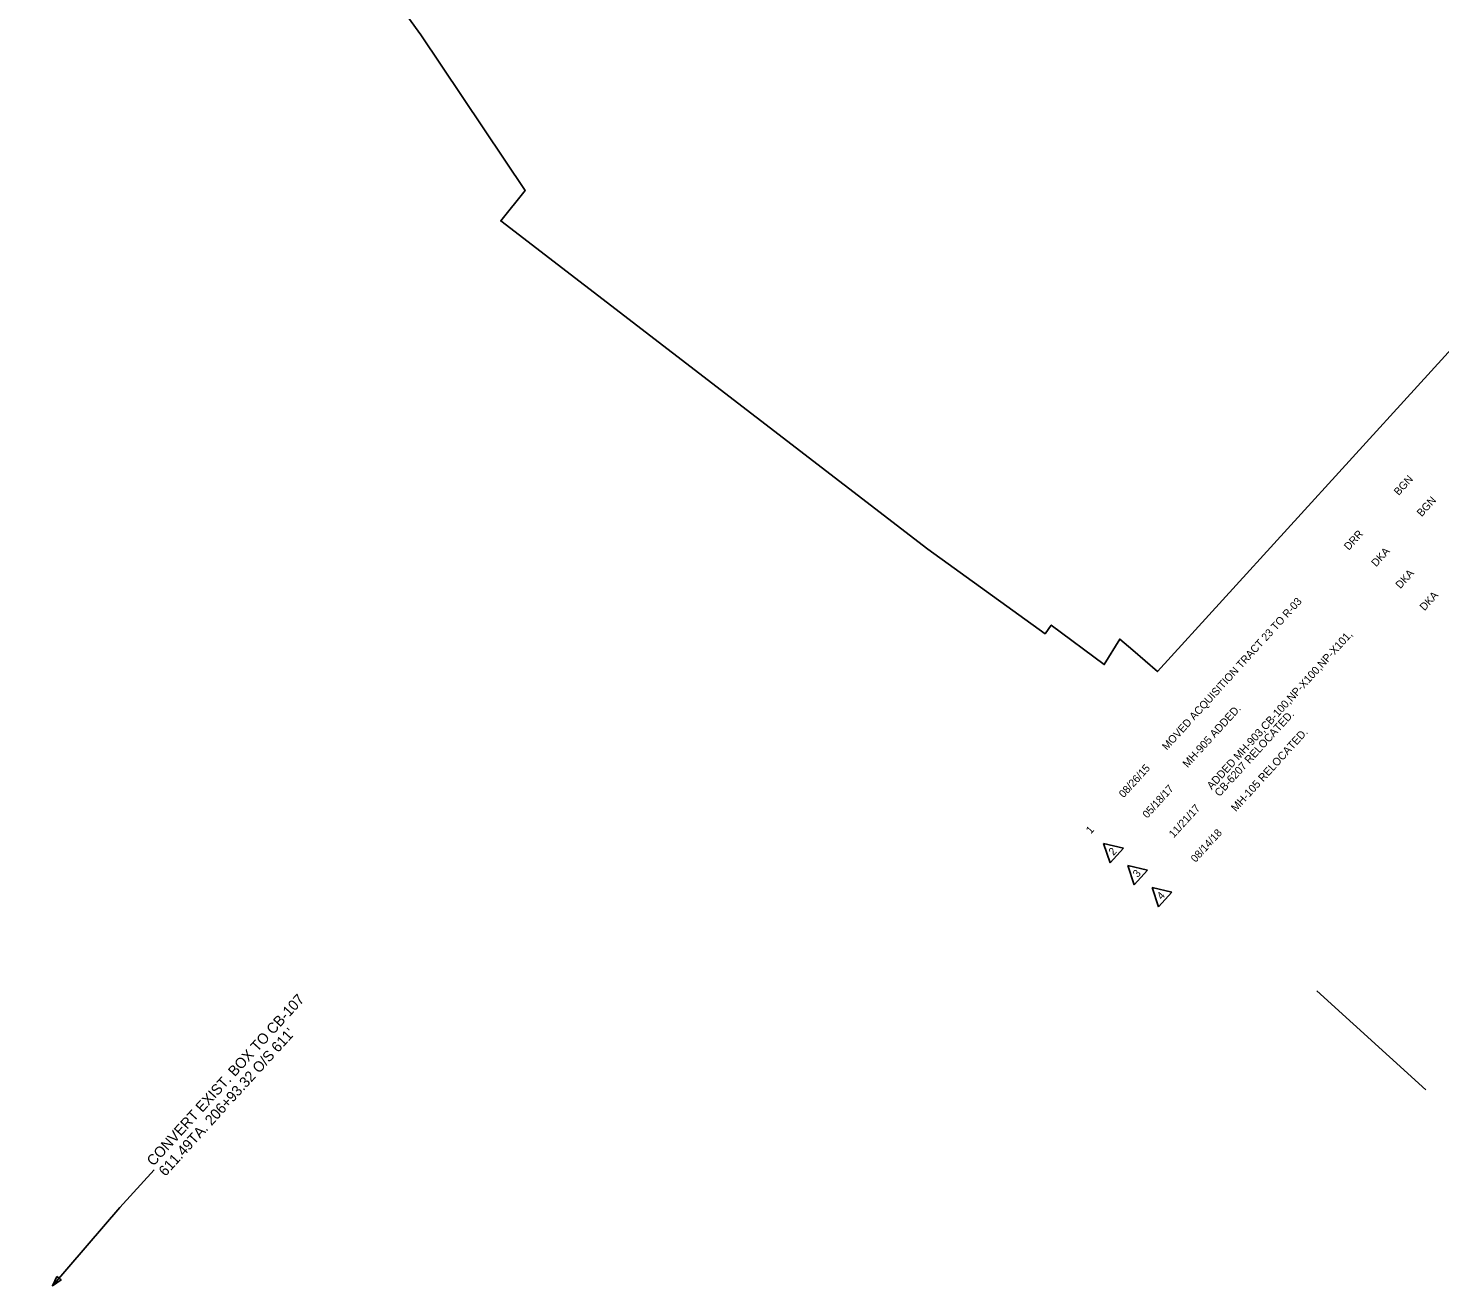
# Model space of a CAD drawing. Extents: x 1608866 to 1610566, y 1091738 to 1093850.
# Drawn here: x 1608866 to 1609672, y 1091738 to 1092457 of the extents above; entities that cross this region are included whole.
import ezdxf

# ---------------------------------------------------------------- set-up
doc = ezdxf.new("R2010")
doc.units = 0
for name, color, linetype in [('Plan_Clip', 7, 'Continuous'), ('RD_SHT_TX', 7, 'Continuous'), ('RD_TX_Drainage', 7, 'Continuous')]:
    doc.layers.add(name, color=color, linetype=linetype)

msp = doc.modelspace()

# ---------------------------------------------------------------- linework, layer by layer
at = {"layer": 'Plan_Clip'}
msp.add_lwpolyline([(1608865.54, 1092773.4), (1609640.55, 1093637.57), (1609735.98, 1093652.25), (1609859.36, 1093621.37), (1610115.12, 1093602.27), (1610196.6, 1093489.1), (1610193.26, 1093486.62), (1610273.82, 1093378.23), (1610243.45, 1093357.42), (1610329.63, 1093200.98), (1610402.66, 1093068.39), (1609510.9, 1092089.32), (1609496.88, 1092101.66), (1609489.45, 1092107.95), (1609480.57, 1092093.35), (1609450.27, 1092115.95), (1609446.7, 1092110.96), (1609379.78, 1092159.35), (1609135.57, 1092347.04), (1609149.57, 1092364.39), (1609089.98, 1092453.43), (1608942.04, 1092657.59), (1608947.36, 1092661.14)], close=True, dxfattribs=at)
msp.add_lwpolyline([(1608865.54, 1092773.4), (1609640.55, 1093637.57), (1609735.98, 1093652.25), (1609859.36, 1093621.37), (1610115.12, 1093602.27), (1610196.6, 1093489.1), (1610193.26, 1093486.62), (1610273.82, 1093378.23), (1610243.45, 1093357.42), (1610329.63, 1093200.98), (1610402.66, 1093068.39), (1609510.9, 1092089.32), (1609496.88, 1092101.66), (1609489.45, 1092107.95), (1609480.57, 1092093.35), (1609450.27, 1092115.95), (1609446.7, 1092110.96), (1609379.78, 1092159.35), (1609135.57, 1092347.04), (1609149.57, 1092364.39), (1609089.98, 1092453.43), (1608942.04, 1092657.59), (1608947.36, 1092661.14)], close=True, dxfattribs=at)
msp.add_lwpolyline([(1608865.54, 1092773.4), (1609640.55, 1093637.57), (1609735.98, 1093652.25), (1609859.36, 1093621.37), (1610115.12, 1093602.27), (1610196.6, 1093489.1), (1610193.26, 1093486.62), (1610273.82, 1093378.23), (1610243.45, 1093357.42), (1610329.63, 1093200.98), (1610402.66, 1093068.39), (1609510.9, 1092089.32), (1609496.88, 1092101.66), (1609489.45, 1092107.95), (1609480.57, 1092093.35), (1609450.27, 1092115.95), (1609446.7, 1092110.96), (1609379.78, 1092159.35), (1609135.57, 1092347.04), (1609149.57, 1092364.39), (1609089.98, 1092453.43), (1608942.04, 1092657.59), (1608947.36, 1092661.14)], close=True, dxfattribs=at)
msp.add_lwpolyline([(1608865.54, 1092773.4), (1609640.55, 1093637.57), (1609735.98, 1093652.25), (1609859.36, 1093621.37), (1610115.12, 1093602.27), (1610196.6, 1093489.1), (1610193.26, 1093486.62), (1610273.82, 1093378.23), (1610243.45, 1093357.42), (1610329.63, 1093200.98), (1610402.66, 1093068.39), (1609510.9, 1092089.32), (1609496.88, 1092101.66), (1609489.45, 1092107.95), (1609480.57, 1092093.35), (1609450.27, 1092115.95), (1609446.7, 1092110.96), (1609379.78, 1092159.35), (1609135.57, 1092347.04), (1609149.57, 1092364.39), (1609089.98, 1092453.43), (1608942.04, 1092657.59), (1608947.36, 1092661.14)], close=True, dxfattribs=at)
msp.add_lwpolyline([(1608865.54, 1092773.4), (1609640.55, 1093637.57), (1609735.98, 1093652.25), (1609859.36, 1093621.37), (1610115.12, 1093602.27), (1610196.6, 1093489.1), (1610193.26, 1093486.62), (1610273.82, 1093378.23), (1610243.45, 1093357.42), (1610329.63, 1093200.98), (1610402.66, 1093068.39), (1609510.9, 1092089.32), (1609496.88, 1092101.66), (1609489.45, 1092107.95), (1609480.57, 1092093.35), (1609450.27, 1092115.95), (1609446.7, 1092110.96), (1609379.78, 1092159.35), (1609135.57, 1092347.04), (1609149.57, 1092364.39), (1609089.98, 1092453.43), (1608942.04, 1092657.59), (1608947.36, 1092661.14)], close=True, dxfattribs=at)
msp.add_lwpolyline([(1608865.54, 1092773.4), (1609640.55, 1093637.57), (1609735.98, 1093652.25), (1609859.36, 1093621.37), (1610115.12, 1093602.27), (1610196.6, 1093489.1), (1610193.26, 1093486.62), (1610273.82, 1093378.23), (1610243.45, 1093357.42), (1610329.63, 1093200.98), (1610402.66, 1093068.39), (1609510.9, 1092089.32), (1609496.88, 1092101.66), (1609489.45, 1092107.95), (1609480.57, 1092093.35), (1609450.27, 1092115.95), (1609446.7, 1092110.96), (1609379.78, 1092159.35), (1609135.57, 1092347.04), (1609149.57, 1092364.39), (1609089.98, 1092453.43), (1608942.04, 1092657.59), (1608947.36, 1092661.14)], close=True, dxfattribs=at)
msp.add_lwpolyline([(1608865.54, 1092773.4), (1609640.55, 1093637.57), (1609735.98, 1093652.25), (1609859.36, 1093621.37), (1610115.12, 1093602.27), (1610196.6, 1093489.1), (1610193.26, 1093486.62), (1610273.82, 1093378.23), (1610243.45, 1093357.42), (1610329.63, 1093200.98), (1610402.66, 1093068.39), (1609510.9, 1092089.32), (1609496.88, 1092101.66), (1609489.45, 1092107.95), (1609480.57, 1092093.35), (1609450.27, 1092115.95), (1609446.7, 1092110.96), (1609379.78, 1092159.35), (1609135.57, 1092347.04), (1609149.57, 1092364.39), (1609089.98, 1092453.43), (1608942.04, 1092657.59), (1608947.36, 1092661.14)], close=True, dxfattribs=at)
msp.add_lwpolyline([(1608865.54, 1092773.4), (1609640.55, 1093637.57), (1609735.98, 1093652.25), (1609859.36, 1093621.37), (1610115.12, 1093602.27), (1610196.6, 1093489.1), (1610193.26, 1093486.62), (1610273.82, 1093378.23), (1610243.45, 1093357.42), (1610329.63, 1093200.98), (1610402.66, 1093068.39), (1609510.9, 1092089.32), (1609496.88, 1092101.66), (1609489.45, 1092107.95), (1609480.57, 1092093.35), (1609450.27, 1092115.95), (1609446.7, 1092110.96), (1609379.78, 1092159.35), (1609135.57, 1092347.04), (1609149.57, 1092364.39), (1609089.98, 1092453.43), (1608942.04, 1092657.59), (1608947.36, 1092661.14)], close=True, dxfattribs=at)
at = {"layer": 'RD_SHT_TX'}
for p, q in [((1609491.53, 1091988.38), (1609480.19, 1091991)), ((1609480.19, 1091991), (1609483.86, 1091979.96)), ((1609483.86, 1091979.96), (1609491.53, 1091988.38)), ((1609505.36, 1091975.8), (1609494.02, 1091978.42)), ((1609494.02, 1091978.42), (1609497.7, 1091967.38)), ((1609497.7, 1091967.38), (1609505.36, 1091975.8)), ((1609519.2, 1091963.22), (1609507.86, 1091965.83)), ((1609507.86, 1091965.83), (1609511.53, 1091954.79)), ((1609511.53, 1091954.79), (1609519.2, 1091963.22)), ((1609664.31, 1091850.11), (1609602.06, 1091906.72))]:
    msp.add_line(p, q, dxfattribs=at)
at = {"layer": 'RD_TX_Drainage'}
msp.add_lwpolyline([(1608937.54, 1091804.49), (1608917.91, 1091782.9), (1608879.36, 1091738.17)], dxfattribs=at)
msp.add_lwpolyline([(1608881.96, 1091743.57), (1608879.36, 1091738.17), (1608884.32, 1091741.55)], close=True, dxfattribs=at)

# ---------------------------------------------------------------- texts
at = {"layer": 'RD_SHT_TX'}
for s, height, rotation, p in [('BGN', 4.4, 47.71377, (1609648.85, 1092189.7)), ('BGN', 4.4, 47.7154, (1609661.99, 1092177.58)), ('DRR', 4.4, 47.71377, (1609620.34, 1092158.35)), ('DKA', 4.4, 47.7154, (1609635.97, 1092148.96)), ('DKA', 4.4, 47.7154, (1609649.8, 1092136.38)), ('MOVED ACQUISITION TRACT 23 TO R-03', 4.4, 47.71377, (1609516.4, 1092044.07)), ('DKA', 4.4, 47.7154, (1609663.63, 1092123.8)), ('ADDED MH-903,CB-100,NP-X100,NP-X101,', 4.5, 47.7154, (1609542.04, 1092021.52)), ('MH-905 ADDED.', 4.5, 47.7154, (1609528.2, 1092034.1)), ('CB-6207 RELOCATED.', 4.5, 47.7154, (1609546.47, 1092017.49)), ('MH-105 RELOCATED.', 4.5, 47.7154, (1609555.87, 1092008.93)), ('08/26/15', 4.4, 47.71377, (1609491.69, 1092016.9)), ('05/18/17', 4.4, 47.7154, (1609505.17, 1092005.15)), ('11/21/17', 4.4, 47.7154, (1609520.29, 1091993.98)), ('1', 4.4, 47.71377, (1609472.88, 1091996.21)), ('08/14/18', 4.4, 47.7154, (1609532.79, 1091979.93)), ('2', 4.4, 47.7154, (1609485.81, 1091983.85)), ('3', 4.4, 47.7154, (1609499.64, 1091971.27)), ('4', 4.4, 47.7154, (1609513.4, 1091958.61))]:
    msp.add_text(s, height=height, rotation=rotation, dxfattribs=at).set_placement(p)
at = {"layer": 'RD_TX_Drainage'}
for s, p in [('CONVERT EXIST. BOX TO CB-107', (1608937.11, 1091806.24)), ("611.49TA. 206+93.32 O/S 611'", (1608943.92, 1091800.36))]:
    msp.add_text(s, height=6, rotation=47.71377, dxfattribs=at).set_placement(p)

doc.saveas('drawing.dxf')
